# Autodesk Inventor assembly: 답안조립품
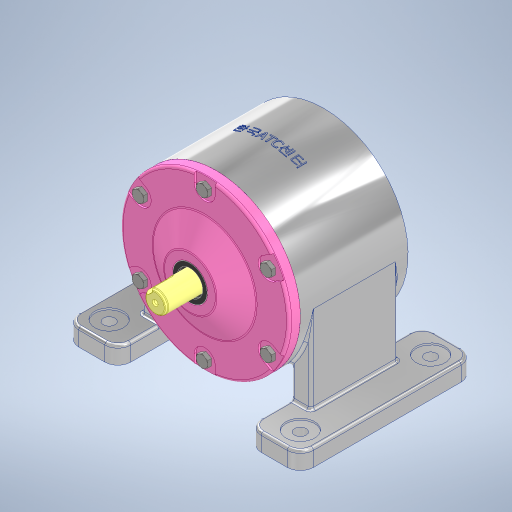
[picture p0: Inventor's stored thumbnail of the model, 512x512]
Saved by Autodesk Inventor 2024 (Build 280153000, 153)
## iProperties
Created: 2025-12
Part Number: 답안조립품
Document SubType Name: Assembly
Designer: Eud07
Author: Eud07
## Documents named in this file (17)
- C:\Users\Eud07\Desktop\751203V1002\답안조립품.iam
- C:\Users\Eud07\Desktop\751203V1002\본체.ipt
- C:\Users\Eud07\Desktop\751203V1002\6각 구멍붙이 볼트 M4x10\6각 구멍붙이 볼트 M4x10.ipt
- C:\Users\Eud07\Desktop\751203V1002\6각 머리 볼트 M8x20\6각 머리 볼트 M8x20.ipt
- C:\Users\Eud07\Desktop\751203V1002\C형 멈춤링 구멍용 42\C형 멈춤링 구멍용 42.ipt
- C:\Users\Eud07\Desktop\751203V1002\구동 기어\구동 기어.ipt
- C:\Users\Eud07\Desktop\751203V1002\기어 축\기어 축.ipt
- C:\Users\Eud07\Desktop\751203V1002\깊은 홈 볼 베어링 6004\깊은 홈 볼 베어링 6004.ipt
- C:\Users\Eud07\Desktop\751203V1002\깊은 홈 볼 베어링 6005\깊은 홈 볼 베어링 6005.ipt
- C:\Users\Eud07\Desktop\751203V1002\엔드 캡\엔드 캡.ipt
- C:\Users\Eud07\Desktop\751203V1002\오일 실 25 40 8\오일 실 25 40 8.ipt
- C:\Users\Eud07\Desktop\751203V1002\종동 기어\종동 기어.ipt
- C:\Users\Eud07\Desktop\751203V1002\출력 축\출력 축.ipt
- C:\Users\Eud07\Desktop\751203V1002\칼라 1\칼라 1.ipt
- C:\Users\Eud07\Desktop\751203V1002\칼라 2\칼라 2.ipt
- C:\Users\Eud07\Desktop\751203V1002\커버\커버.ipt
- C:\Users\Eud07\Desktop\751203V1002\평행 키 6x6x16\평행 키 6x6x16.ipt
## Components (9 placed, 4 different names)
1. 6각 구멍붙이 볼트 M4x10:1
2. C형 멈춤링 구멍용 42:1
3. 구동 기어:1
4. 6각 머리 볼트 M8x20:1
5. 6각 머리 볼트 M8x20:2
6. 6각 머리 볼트 M8x20:3
7. 6각 머리 볼트 M8x20:4
8. 6각 머리 볼트 M8x20:5
9. 6각 머리 볼트 M8x20:6
